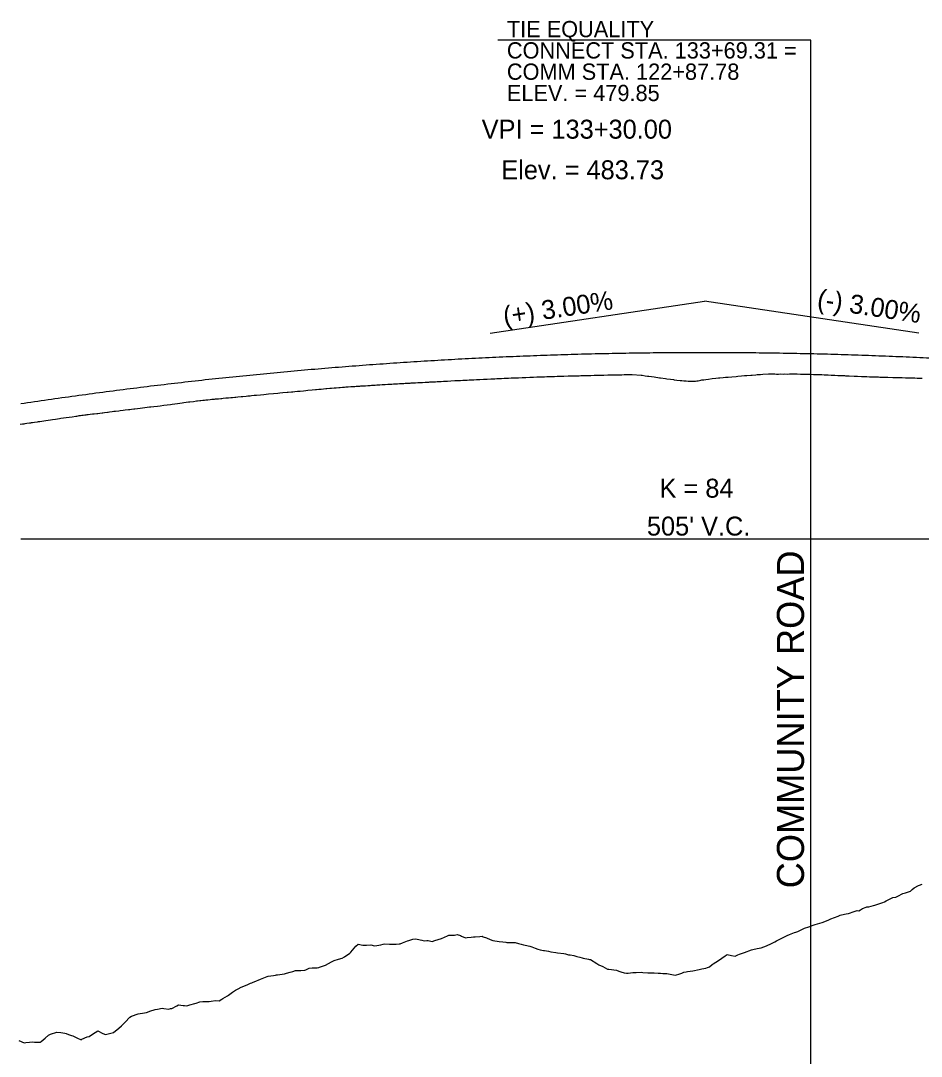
# Model space of a CAD drawing. Extents: x 2017200 to 2047700, y 854850 to 893350.
# Drawn here: x 2022577.5 to 2022910.1, y 865289.7 to 865672.2 of the extents above; entities that cross this region are included whole.
import ezdxf

# ---------------------------------------------------------------- set-up
doc = ezdxf.new("R2010")
doc.units = 0
for name, color, linetype in [('RD_DDB_GradeTX', 7, 'Continuous'), ('RD_DDB_Profile_Elev', 7, 'Continuous'), ('RD_DDB_Profile_EX', 7, 'Continuous'), ('RD_DDB_Profile_Lbl', 7, 'Continuous'), ('RD_DDB_Profile_PR', 7, 'Continuous'), ('RD_DDB_VCLbl', 7, 'Continuous'), ('RD_PD_NON-PLOTTING', 7, 'Continuous')]:
    doc.layers.add(name, color=color, linetype=linetype)

msp = doc.modelspace()

# ---------------------------------------------------------------- linework, layer by layer
at = {"layer": 'RD_DDB_GradeTX'}
for p in [(2022750.89, 865556.78), (2022909.11, 865556.78)]:
    msp.add_line(p, (2022830, 865568.65), dxfattribs=at)
at = {"layer": 'RD_DDB_Profile_Elev'}
msp.add_lwpolyline([(2022577.3, 865523.15), (2022578.18, 865523.27), (2022578.75, 865523.36), (2022579.16, 865523.42), (2022579.73, 865523.5), (2022580.69, 865523.64), (2022581.18, 865523.71), (2022581.53, 865523.76), (2022581.85, 865523.81), (2022582.64, 865523.92), (2022583.71, 865524.08), (2022584.02, 865524.12), (2022584.58, 865524.2), (2022586.76, 865524.52), (2022588.46, 865524.76), (2022589.29, 865524.88), (2022590.4, 865525.05), (2022591.84, 865525.26), (2022592.34, 865525.34), (2022594.32, 865525.63), (2022596.45, 865525.94), (2022597.81, 865526.14), (2022598.17, 865526.19), (2022598.69, 865526.27), (2022599.09, 865526.33), (2022599.52, 865526.38), (2022600.11, 865526.46), (2022600.61, 865526.52), (2022601.2, 865526.59), (2022601.71, 865526.66), (2022602.09, 865526.7), (2022602.44, 865526.75), (2022603.15, 865526.84), (2022603.99, 865526.94), (2022604.66, 865527.03), (2022605.62, 865527.15), (2022605.94, 865527.18), (2022606.68, 865527.28), (2022607.55, 865527.39), (2022607.88, 865527.43), (2022608.41, 865527.49), (2022609.49, 865527.63), (2022609.82, 865527.67), (2022610.28, 865527.73), (2022611.3, 865527.85), (2022611.93, 865527.93), (2022612.55, 865528.01), (2022613.7, 865528.15), (2022614.27, 865528.22), (2022615.34, 865528.35), (2022616.08, 865528.44), (2022617.29, 865528.59), (2022617.83, 865528.65), (2022618.47, 865528.73), (2022619.23, 865528.82), (2022619.61, 865528.87), (2022621.56, 865529.11), (2022623.35, 865529.32), (2022625.09, 865529.54), (2022625.61, 865529.6), (2022626.68, 865529.73), (2022627.99, 865529.88), (2022628.97, 865530), (2022630.37, 865530.19), (2022631.55, 865530.35), (2022632.76, 865530.51), (2022633.39, 865530.59), (2022635.4, 865530.86), (2022637.07, 865531.08), (2022637.69, 865531.15), (2022639.44, 865531.38), (2022639.9, 865531.44), (2022641.29, 865531.61), (2022642.45, 865531.76), (2022642.78, 865531.8), (2022643.7, 865531.91), (2022644.05, 865531.95), (2022644.71, 865532.03), (2022645.05, 865532.06), (2022645.43, 865532.11), (2022645.85, 865532.15), (2022646.65, 865532.23), (2022647.47, 865532.31), (2022648.03, 865532.36), (2022648.51, 865532.4), (2022649.04, 865532.45), (2022649.43, 865532.49), (2022649.73, 865532.52), (2022650.18, 865532.56), (2022650.53, 865532.59), (2022651.41, 865532.68), (2022651.81, 865532.71), (2022652.21, 865532.75), (2022653.25, 865532.85), (2022653.88, 865532.91), (2022654.19, 865532.94), (2022655.05, 865533.02), (2022655.73, 865533.09), (2022656.57, 865533.17), (2022656.97, 865533.21), (2022657.65, 865533.27), (2022658.96, 865533.39), (2022659.53, 865533.45), (2022660.71, 865533.56), (2022661.34, 865533.62), (2022662.27, 865533.71), (2022662.74, 865533.75), (2022663.72, 865533.84), (2022664.23, 865533.89), (2022664.59, 865533.92), (2022666.1, 865534.06), (2022667.26, 865534.17), (2022668.99, 865534.33), (2022670.87, 865534.51), (2022672.5, 865534.66), (2022673.25, 865534.73), (2022674.26, 865534.82), (2022675.92, 865534.97), (2022676.26, 865535), (2022677.44, 865535.11), (2022678.01, 865535.16), (2022678.7, 865535.23), (2022679.66, 865535.32), (2022680.66, 865535.41), (2022681.96, 865535.54), (2022682.77, 865535.62), (2022683.51, 865535.69), (2022685.16, 865535.84), (2022686.33, 865535.95), (2022686.67, 865535.98), (2022687.54, 865536.07), (2022688.05, 865536.11), (2022688.43, 865536.15), (2022690.12, 865536.31), (2022690.49, 865536.34), (2022691.67, 865536.45), (2022691.99, 865536.48), (2022692.3, 865536.5), (2022693.23, 865536.59), (2022694.05, 865536.66), (2022694.92, 865536.73), (2022695.52, 865536.77), (2022696.29, 865536.83), (2022696.65, 865536.86), (2022697.06, 865536.89), (2022697.55, 865536.92), (2022697.97, 865536.95), (2022698.43, 865536.98), (2022699.45, 865537.05), (2022699.88, 865537.08), (2022700.88, 865537.15), (2022701.35, 865537.18), (2022701.83, 865537.21), (2022702.75, 865537.27), (2022703.1, 865537.29), (2022703.43, 865537.31), (2022704.34, 865537.37), (2022704.84, 865537.4), (2022705.66, 865537.46), (2022706.59, 865537.51), (2022707.03, 865537.54), (2022707.82, 865537.59), (2022708.39, 865537.63), (2022708.97, 865537.66), (2022709.28, 865537.68), (2022709.69, 865537.71), (2022710.06, 865537.73), (2022711.03, 865537.79), (2022711.51, 865537.81), (2022712.05, 865537.85), (2022713.04, 865537.9), (2022713.74, 865537.95), (2022714.58, 865537.99), (2022715.18, 865538.03), (2022716.12, 865538.08), (2022716.64, 865538.11), (2022717.38, 865538.16), (2022717.92, 865538.19), (2022718.5, 865538.22), (2022718.99, 865538.25), (2022719.47, 865538.27), (2022720.15, 865538.31), (2022720.57, 865538.34), (2022720.88, 865538.35), (2022721.38, 865538.38), (2022721.72, 865538.4), (2022722.88, 865538.46), (2022723.26, 865538.48), (2022724.13, 865538.53), (2022724.45, 865538.55), (2022725.84, 865538.63), (2022726.88, 865538.68), (2022727.25, 865538.7), (2022728.24, 865538.76), (2022728.61, 865538.78), (2022729.52, 865538.82), (2022729.87, 865538.84), (2022730.65, 865538.88), (2022731.27, 865538.92), (2022731.57, 865538.93), (2022732.79, 865539), (2022733.63, 865539.04), (2022734.86, 865539.1), (2022735.17, 865539.12), (2022736.38, 865539.18), (2022737.84, 865539.26), (2022739.32, 865539.33), (2022739.94, 865539.36), (2022740.76, 865539.4), (2022742.32, 865539.48), (2022743.09, 865539.52), (2022744.01, 865539.56), (2022744.83, 865539.6), (2022745.84, 865539.65), (2022747.08, 865539.71), (2022748.36, 865539.77), (2022749.75, 865539.83), (2022751.16, 865539.9), (2022751.85, 865539.93), (2022752.55, 865539.96), (2022753.33, 865540), (2022753.87, 865540.02), (2022754.23, 865540.04), (2022755.07, 865540.08), (2022756.09, 865540.12), (2022756.87, 865540.16), (2022757.64, 865540.19), (2022758.66, 865540.24), (2022758.99, 865540.25), (2022759.86, 865540.29), (2022761.37, 865540.35), (2022762.65, 865540.4), (2022764.06, 865540.46), (2022765.5, 865540.51), (2022766.14, 865540.54), (2022766.88, 865540.56), (2022768.09, 865540.61), (2022768.52, 865540.62), (2022768.99, 865540.64), (2022769.86, 865540.67), (2022770.9, 865540.7), (2022771.75, 865540.74), (2022773.28, 865540.79), (2022774.66, 865540.83), (2022775.66, 865540.87), (2022776.49, 865540.88), (2022778.06, 865540.93), (2022779.7, 865540.98), (2022780.43, 865541), (2022781.15, 865541.02), (2022782.51, 865541.06), (2022782.81, 865541.07), (2022783.41, 865541.09), (2022783.71, 865541.09), (2022784.39, 865541.11), (2022784.71, 865541.11), (2022785.39, 865541.13), (2022786.3, 865541.17), (2022786.65, 865541.17), (2022787.73, 865541.2), (2022788.08, 865541.2), (2022789.27, 865541.24), (2022789.61, 865541.24), (2022789.95, 865541.25), (2022790.86, 865541.28), (2022791.44, 865541.28), (2022792.34, 865541.31), (2022792.9, 865541.32), (2022794.31, 865541.35), (2022794.72, 865541.36), (2022795.4, 865541.39), (2022795.71, 865541.38), (2022796.65, 865541.4), (2022797.38, 865541.43), (2022797.77, 865541.41), (2022798.26, 865541.43), (2022798.8, 865541.44), (2022799.5, 865541.45), (2022800.31, 865541.47), (2022801.15, 865541.48), (2022801.98, 865541.49), (2022802.73, 865541.51), (2022803.35, 865541.52), (2022806.63, 865541.3), (2022807.05, 865541.24), (2022808.09, 865541.09), (2022809.01, 865540.95), (2022809.49, 865540.89), (2022811.39, 865540.61), (2022813.35, 865540.34), (2022813.77, 865540.28), (2022815.63, 865540), (2022816.15, 865539.93), (2022817.42, 865539.78), (2022818.54, 865539.64), (2022818.87, 865539.6), (2022819.79, 865539.48), (2022821.04, 865539.35), (2022821.64, 865539.3), (2022822.41, 865539.23), (2022823.3, 865539.15), (2022823.93, 865539.09), (2022826.27, 865539.09), (2022826.66, 865539.12), (2022827.15, 865539.15), (2022827.63, 865539.18), (2022828.68, 865539.46), (2022829.09, 865539.51), (2022829.72, 865539.6), (2022830.54, 865539.71), (2022831.51, 865539.84), (2022832.83, 865540.01), (2022834.17, 865540.15), (2022835.21, 865540.25), (2022835.62, 865540.29), (2022836.92, 865540.42), (2022837.77, 865540.5), (2022838.76, 865540.59), (2022840.12, 865540.71), (2022841.69, 865540.85), (2022842.35, 865540.91), (2022843.68, 865541.01), (2022844.74, 865541.1), (2022845.23, 865541.15), (2022845.63, 865541.17), (2022847.12, 865541.3), (2022847.61, 865541.32), (2022848.95, 865541.44), (2022849.52, 865541.47), (2022850.67, 865541.56), (2022851.55, 865541.63), (2022853.67, 865541.74), (2022854.44, 865541.73), (2022854.91, 865541.73), (2022855.33, 865541.72), (2022855.94, 865541.72), (2022856.65, 865541.7), (2022857.35, 865541.69), (2022857.96, 865541.72), (2022859.03, 865541.71), (2022859.52, 865541.74), (2022860.63, 865541.71), (2022861.41, 865541.74), (2022862.3, 865541.72), (2022862.98, 865541.76), (2022863.79, 865541.74), (2022864.25, 865541.74), (2022865.43, 865541.71), (2022866.54, 865541.69), (2022867.45, 865541.67), (2022868.04, 865541.65), (2022868.61, 865541.64), (2022869.35, 865541.62), (2022870.33, 865541.59), (2022870.94, 865541.58), (2022871.53, 865541.55), (2022872.81, 865541.5), (2022873.32, 865541.49), (2022874.15, 865541.45), (2022875.7, 865541.37), (2022876.85, 865541.33), (2022878.14, 865541.27), (2022879.27, 865541.21), (2022879.93, 865541.19), (2022880.59, 865541.18), (2022880.91, 865541.14), (2022881.78, 865541.11), (2022882.11, 865541.08), (2022882.84, 865541.06), (2022883.15, 865541.05), (2022883.47, 865541.01), (2022885.23, 865540.94), (2022886.47, 865540.89), (2022887.99, 865540.83), (2022889.57, 865540.77), (2022889.99, 865540.76), (2022890.98, 865540.72), (2022892.37, 865540.67), (2022893.47, 865540.63), (2022894.23, 865540.61), (2022894.75, 865540.6), (2022895.06, 865540.59), (2022896.25, 865540.56), (2022897.14, 865540.53), (2022897.71, 865540.52), (2022899.52, 865540.47), (2022901.18, 865540.42), (2022901.9, 865540.4), (2022903.01, 865540.37), (2022904.28, 865540.34), (2022904.78, 865540.32), (2022906.66, 865540.27), (2022907.68, 865540.24), (2022908.57, 865540.21), (2022909.31, 865540.18), (2022909.78, 865540.16), (2022910.35, 865540.13)], dxfattribs=at)
at = {"layer": 'RD_DDB_Profile_EX'}
msp.add_lwpolyline([(2022576.81, 865295.56), (2022578.75, 865294.69), (2022579.36, 865294.76), (2022580.69, 865294.87), (2022581.76, 865294.96), (2022582.64, 865294.93), (2022584.76, 865294.9), (2022585.08, 865295.17), (2022586.52, 865296.43), (2022587.76, 865297.53), (2022588.46, 865297.79), (2022590.88, 865298.61), (2022592.34, 865298.43), (2022593.77, 865298.26), (2022594.29, 865298.07), (2022595.1, 865297.78), (2022596.23, 865297.38), (2022596.77, 865297.2), (2022598.17, 865296.54), (2022599.77, 865295.8), (2022600.11, 865295.95), (2022602.05, 865296.83), (2022602.77, 865297.04), (2022603.99, 865297.87), (2022605.94, 865299.09), (2022607.88, 865298.15), (2022608.77, 865297.7), (2022609.82, 865297.95), (2022611.77, 865298.42), (2022613.7, 865300.01), (2022614.77, 865300.89), (2022616.08, 865302.32), (2022617.77, 865304.17), (2022618.47, 865304.45), (2022620.9, 865305.41), (2022623.23, 865305.75), (2022623.99, 865305.86), (2022625.61, 865306.41), (2022626.78, 865306.81), (2022627.1, 865306.9), (2022627.99, 865307.08), (2022629.78, 865307.43), (2022630.37, 865307.35), (2022632.26, 865307.13), (2022632.78, 865307.28), (2022633.36, 865307.38), (2022635.14, 865308.29), (2022635.79, 865308.63), (2022637.52, 865308.48), (2022637.99, 865308.45), (2022638.79, 865308.37), (2022639.9, 865308.66), (2022641.8, 865309.13), (2022642.28, 865309.29), (2022643.69, 865309.74), (2022644.8, 865309.92), (2022646.52, 865309.91), (2022647.05, 865309.96), (2022647.81, 865310.04), (2022649.43, 865310.23), (2022650.82, 865310.19), (2022651.81, 865310.81), (2022652.15, 865311.03), (2022653.83, 865312.06), (2022654.19, 865312.29), (2022655.77, 865313.32), (2022656.84, 865314.07), (2022657.75, 865314.59), (2022658.96, 865315.18), (2022659.85, 865315.62), (2022661.34, 865316.25), (2022662.32, 865316.67), (2022662.86, 865316.82), (2022663.3, 865317.09), (2022663.72, 865317.24), (2022666.1, 865318.14), (2022668.48, 865319.1), (2022668.88, 865319.25), (2022670.87, 865319.56), (2022671.57, 865319.67), (2022671.9, 865319.78), (2022672.29, 865319.8), (2022673.25, 865319.92), (2022674.91, 865320.14), (2022675.63, 865320.34), (2022677.04, 865320.73), (2022678.01, 865321.01), (2022679.03, 865321.42), (2022680.39, 865321.35), (2022680.95, 865321.33), (2022682.43, 865321.43), (2022682.77, 865321.61), (2022683.97, 865322.24), (2022685.18, 865322.32), (2022686.99, 865322.37), (2022687.54, 865322.48), (2022687.88, 865322.55), (2022690.01, 865323.39), (2022692.3, 865324.6), (2022693.25, 865325.06), (2022694.88, 865325.51), (2022696.25, 865325.94), (2022697.06, 865326.46), (2022699.09, 865327.74), (2022699.45, 865328.18), (2022701.25, 865330.39), (2022702.12, 865331.1), (2022703.9, 865330.67), (2022704.21, 865330.67), (2022705.16, 865330.67), (2022706.85, 865330.82), (2022708.19, 865330.52), (2022708.97, 865330.65), (2022710.43, 865330.9), (2022711.36, 865331.14), (2022711.81, 865331.26), (2022713.74, 865331.13), (2022714.26, 865331.1), (2022715.48, 865331.08), (2022716.12, 865331.12), (2022717.3, 865331.2), (2022717.66, 865331.24), (2022718.5, 865331.57), (2022720.35, 865332.3), (2022720.88, 865332.47), (2022722.26, 865332.92), (2022723.39, 865333.09), (2022725, 865332.71), (2022725.65, 865332.55), (2022726.44, 865332.36), (2022727.44, 865332.5), (2022728.03, 865332.39), (2022729.49, 865332.11), (2022730.41, 865332.4), (2022732.93, 865333.2), (2022735.17, 865334.21), (2022735.59, 865334.41), (2022737.73, 865334.43), (2022738.65, 865334.69), (2022739.94, 865334.24), (2022740.29, 865334.11), (2022741.7, 865333.45), (2022742.32, 865333.52), (2022743.84, 865333.68), (2022744.77, 865333.81), (2022745.38, 865333.82), (2022747.08, 865333.98), (2022747.92, 865334.05), (2022748.33, 865333.85), (2022749.46, 865333.38), (2022750.9, 865332.78), (2022751.85, 865332.51), (2022754.23, 865332.06), (2022755.5, 865331.93), (2022756.61, 865331.81), (2022757.04, 865331.77), (2022758.01, 865331.73), (2022758.99, 865331.69), (2022760.11, 865331.65), (2022761.37, 865331.34), (2022762.29, 865331.11), (2022763.19, 865330.89), (2022763.76, 865330.77), (2022765.52, 865330.37), (2022766.27, 865330.12), (2022767.49, 865329.66), (2022768.52, 865329.31), (2022769.36, 865329.01), (2022770.5, 865328.8), (2022770.9, 865328.73), (2022772.45, 865328.47), (2022773.28, 865328.22), (2022775.16, 865328.02), (2022775.67, 865327.95), (2022778.05, 865327.59), (2022778.63, 865327.5), (2022779.81, 865327.2), (2022780.43, 865327.1), (2022781.73, 865326.87), (2022782.81, 865326.59), (2022784, 865326.28), (2022784.83, 865326.04), (2022785.19, 865325.97), (2022787.15, 865325.59), (2022787.57, 865325.48), (2022787.94, 865325.38), (2022790.22, 865323.96), (2022791.05, 865323.43), (2022792.5, 865322.8), (2022794.16, 865321.85), (2022794.72, 865321.8), (2022797.53, 865321.43), (2022798.42, 865321.09), (2022799.48, 865320.73), (2022799.96, 865320.57), (2022800.4, 865320.56), (2022801.19, 865320.35), (2022801.86, 865320.44), (2022803.52, 865320.67), (2022804.25, 865320.66), (2022804.8, 865320.66), (2022806.65, 865320.76), (2022807.21, 865320.62), (2022809.1, 865320.54), (2022810.08, 865320.48), (2022811.39, 865320.45), (2022812.92, 865320.42), (2022813.77, 865320.36), (2022814.6, 865320.31), (2022816.15, 865320.27), (2022818.54, 865319.78), (2022819.27, 865319.67), (2022820.92, 865320.14), (2022821.61, 865320.33), (2022822.35, 865320.73), (2022823.3, 865320.88), (2022823.8, 865320.96), (2022825.68, 865321.2), (2022828.06, 865321.69), (2022829.01, 865321.93), (2022830.45, 865322.27), (2022831.12, 865322.43), (2022831.83, 865322.74), (2022832.83, 865323.54), (2022833.25, 865323.88), (2022835.21, 865325.08), (2022837.59, 865326.84), (2022838.35, 865327.27), (2022839.97, 865326.95), (2022841.35, 865326.67), (2022842.35, 865327.12), (2022842.96, 865327.38), (2022844.74, 865328.04), (2022847.36, 865329.01), (2022847.92, 865329.17), (2022849.5, 865329.48), (2022850.91, 865329.76), (2022851.88, 865330.06), (2022852.3, 865330.18), (2022854.26, 865331.08), (2022856.05, 865331.98), (2022856.65, 865332.31), (2022857.31, 865332.69), (2022858.07, 865333.04), (2022859.03, 865333.54), (2022860.52, 865334.32), (2022861.41, 865334.66), (2022863.27, 865335.38), (2022863.79, 865335.55), (2022864.48, 865335.83), (2022866.26, 865336.65), (2022866.95, 865336.95), (2022868.55, 865337.52), (2022870.18, 865338.13), (2022870.94, 865338.36), (2022872.65, 865338.87), (2022873.41, 865339.1), (2022875.7, 865339.9), (2022876.65, 865340.48), (2022878.08, 865340.99), (2022879.4, 865341.47), (2022880.1, 865341.82), (2022880.6, 865341.9), (2022882.39, 865342.36), (2022883.14, 865342.42), (2022885.23, 865343.13), (2022886.4, 865343.54), (2022886.98, 865343.39), (2022887.61, 865343.77), (2022888.33, 865344.21), (2022889.66, 865344.8), (2022889.99, 865344.85), (2022890.66, 865344.94), (2022892.37, 865345.36), (2022892.93, 865345.5), (2022894.75, 865346.14), (2022895.88, 865346.53), (2022896.46, 865346.79), (2022897.14, 865347.12), (2022899.52, 865348.28), (2022900.65, 865348.47), (2022901.9, 865349.12), (2022902.78, 865349.58), (2022903.24, 865349.77), (2022904.28, 865350.11), (2022906.07, 865350.7), (2022906.66, 865351.24), (2022907.45, 865351.96), (2022909.04, 865352.72), (2022909.37, 865352.88), (2022910.44, 865353.25)], dxfattribs=at)
at = {"layer": 'RD_DDB_Profile_Lbl'}
msp.add_lwpolyline([(2022869.31, 865549.25), (2022869.31, 865665.02), (2022753.66, 865665.02)], dxfattribs=at)
at = {"layer": 'RD_DDB_Profile_PR'}
msp.add_spline([(2022577.5, 865530.78), (2022587.6, 865532.26), (2022597.7, 865533.68), (2022607.8, 865535.05), (2022617.9, 865536.35), (2022628, 865537.59), (2022638.1, 865538.77), (2022648.2, 865539.9), (2022658.3, 865540.96), (2022668.4, 865541.96), (2022678.5, 865542.9), (2022688.6, 865543.77), (2022698.7, 865544.59), (2022708.8, 865545.35), (2022718.9, 865546.05), (2022729, 865546.68), (2022739.1, 865547.26), (2022749.2, 865547.77), (2022759.3, 865548.23), (2022769.4, 865548.62), (2022779.5, 865548.96), (2022789.6, 865549.23), (2022799.7, 865549.44), (2022809.8, 865549.59), (2022819.9, 865549.68), (2022830, 865549.71), (2022840.1, 865549.68), (2022850.2, 865549.59), (2022860.3, 865549.44), (2022870.4, 865549.23), (2022880.5, 865548.96), (2022890.6, 865548.62), (2022900.7, 865548.23), (2022910.8, 865547.77), (2022920.9, 865547.26), (2022931, 865546.68), (2022941.1, 865546.05), (2022951.2, 865545.35), (2022961.3, 865544.59), (2022971.4, 865543.77), (2022981.5, 865542.9), (2022991.6, 865541.96), (2023001.7, 865540.96), (2023011.8, 865539.9), (2023021.9, 865538.77), (2023032, 865537.59), (2023042.1, 865536.35), (2023052.2, 865535.05), (2023062.3, 865533.68), (2023072.4, 865532.26), (2023082.5, 865530.78)], degree=3, dxfattribs=at)
at = {"layer": 'RD_DDB_VCLbl'}
msp.add_line((2022577.5, 865480.78), (2023082.5, 865480.78), dxfattribs=at)
at = {"layer": 'RD_PD_NON-PLOTTING'}
msp.add_line((2022869.31, 865100), (2022869.31, 865569.19), dxfattribs=at)

# ---------------------------------------------------------------- texts
at = {"layer": 'RD_DDB_GradeTX'}
for s, rotation, p in [('(+) 3.00%', 8.5308, (2022756.2, 865559.6)), ('(-) 3.00%', 351.4692, (2022871.33, 865566.17))]:
    msp.add_text(s, height=7, rotation=rotation, dxfattribs=at).set_placement(p)
at = {"layer": 'RD_DDB_Profile_Lbl'}
for s, p in [('TIE EQUALITY', (2022757.04, 865666.13)), ('CONNECT STA. 133+69.31 =', (2022757.04, 865658.26)), ('COMM STA. 122+87.78', (2022757.04, 865650.4)), ('ELEV. = 479.85', (2022757.04, 865642.53))]:
    msp.add_text(s, height=6, rotation=360, dxfattribs=at).set_placement(p)
for s, p in [('VPI = 133+30.00', (2022747.74, 865628.65)), ('Elev. = 483.73', (2022754.97, 865613.65))]:
    msp.add_text(s, height=7, dxfattribs=at).set_placement(p)
at = {"layer": 'RD_DDB_VCLbl'}
for s, p in [('K = 84', (2022813.41, 865496.03)), ("505' V.C.", (2022808.75, 865482.03))]:
    msp.add_text(s, height=7, dxfattribs=at).set_placement(p)
at = {"layer": 'RD_PD_NON-PLOTTING'}
msp.add_text('COMMUNITY ROAD', height=10, rotation=90, dxfattribs=at).set_placement((2022866.76, 865351.73))

doc.saveas('drawing.dxf')
